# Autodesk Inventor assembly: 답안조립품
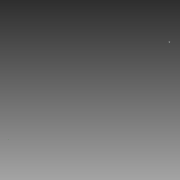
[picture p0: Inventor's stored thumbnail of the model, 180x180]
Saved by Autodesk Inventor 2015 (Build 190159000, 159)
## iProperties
Created: 2016-02
Part Number: 답안조립품
Document SubType Name: Assembly
Designer: Administrator
Author: Administrator
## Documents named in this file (19)
- C:\Users\Administrator\Desktop\460219V1015\답안조립품.iam
- C:\Users\Administrator\Desktop\460219V1015\본체.ipt
- C:\Users\Administrator\Desktop\460219V1015\V-벨트풀리.ipt
- C:\Users\Administrator\Desktop\460219V1015\고정핀.ipt
- C:\Users\Administrator\Desktop\460219V1015\뒤커버.ipt
- C:\Users\Administrator\Desktop\460219V1015\링크.ipt
- C:\Users\Administrator\Desktop\460219V1015\멈춤링 6 x 5.ipt
- C:\Users\Administrator\Desktop\460219V1015\멈춤링 15 x 1.ipt
- C:\Users\Administrator\Desktop\460219V1015\베어링 15 x 35 x 11.ipt
- C:\Users\Administrator\Desktop\460219V1015\볼트 M3 x 8.ipt
- C:\Users\Administrator\Desktop\460219V1015\볼트 M4 x 10.ipt
- C:\Users\Administrator\Desktop\460219V1015\볼트 M6 x 12.ipt
- C:\Users\Administrator\Desktop\460219V1015\상부부시.ipt
- C:\Users\Administrator\Desktop\460219V1015\슬라이드바.ipt
- C:\Users\Administrator\Desktop\460219V1015\앞커버.ipt
- C:\Users\Administrator\Desktop\460219V1015\오일실 15 25 7.ipt
- C:\Users\Administrator\Desktop\460219V1015\와셔.ipt
- C:\Users\Administrator\Desktop\460219V1015\키 5 x 5 x 14.ipt
- C:\Users\Administrator\Desktop\460219V1015\편심축.ipt
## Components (12 placed, 5 different names)
1. V-벨트풀리:1
2. 고정핀:1
3. ISO 4762 M3 x 8:1
4. ISO 4018 M6 x 12:1
5. ISO 4762 M4 x 10:2
6. ISO 4762 M4 x 10:3
7. ISO 4762 M4 x 10:4
8. ISO 4762 M4 x 10:5
9. ISO 4762 M4 x 10:6
10. ISO 4762 M4 x 10:7
11. ISO 4762 M4 x 10:8
12. ISO 4762 M4 x 10:9
